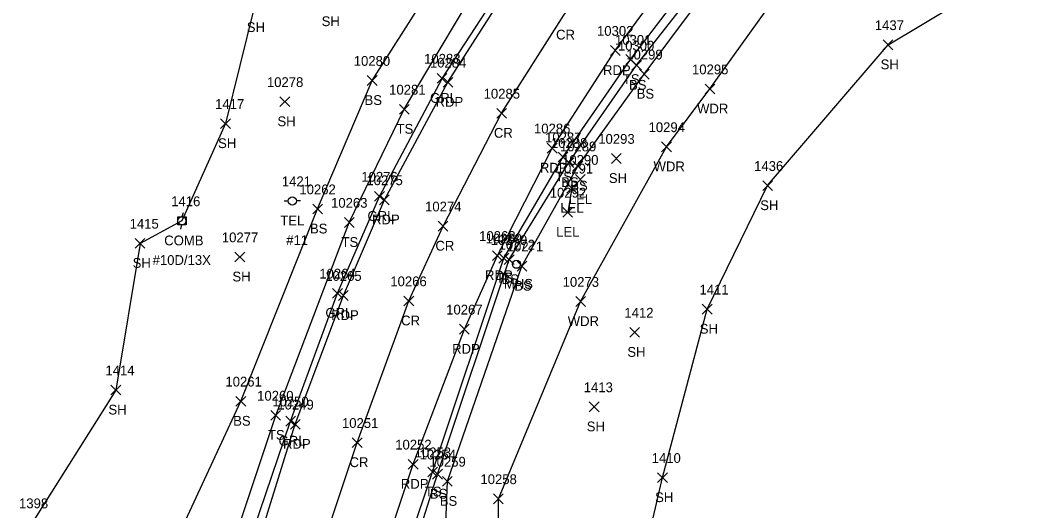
# Model space of a CAD drawing. Extents: x 1651685 to 1653558, y 889533 to 891085.
# Drawn here: x 1652735.7 to 1652940.5, y 890489.8 to 890590.1 of the extents above; entities that cross this region are included whole.
import ezdxf

# ---------------------------------------------------------------- set-up
doc = ezdxf.new("R2010")
doc.units = 0
for name, color, linetype in [('L_A', 7, 'Continuous'), ('L_I', 7, 'Continuous'), ('L_TIC', 7, 'Continuous'), ('LARO', 7, 'Continuous'), ('LAWA', 7, 'Continuous'), ('LELB', 7, 'Continuous'), ('LSOGP', 7, 'Continuous'), ('P_A', 7, 'Continuous'), ('P_I', 7, 'Continuous'), ('P_TIC', 7, 'Continuous'), ('PET', 7, 'Continuous'), ('PRC', 7, 'Continuous'), ('R_A', 7, 'Continuous'), ('R_I', 7, 'Continuous'), ('R_TIC', 7, 'Continuous'), ('RGR', 7, 'Continuous'), ('U_A', 7, 'Continuous'), ('U_C', 7, 'Continuous'), ('U_I', 7, 'Continuous'), ('UP', 7, 'Continuous'), ('USMH', 7, 'Continuous')]:
    doc.layers.add(name, color=color, linetype=linetype)

msp = doc.modelspace()

# ---------------------------------------------------------------- linework, layer by layer
at = {"layer": 'L_TIC'}
for points in [[(1652911.99, 890584.04), (1652913.99, 890586.04)], [(1652913.99, 890584.04), (1652911.99, 890586.04)], [(1652859.39, 890581.03), (1652861.39, 890583.03)], [(1652861.39, 890581.03), (1652859.39, 890583.03)], [(1652860.63, 890579.86), (1652862.63, 890581.86)], [(1652862.63, 890579.86), (1652860.63, 890581.86)], [(1652862.19, 890578.04), (1652864.19, 890580.04)], [(1652864.19, 890578.04), (1652862.19, 890580.04)], [(1652806.59, 890576.74), (1652808.59, 890578.74)], [(1652808.59, 890576.74), (1652806.59, 890578.74)], [(1652875.6, 890575.01), (1652877.6, 890577.01)], [(1652877.6, 890575.01), (1652875.6, 890577.01)], [(1652788.76, 890572.41), (1652790.76, 890574.41)], [(1652790.76, 890572.41), (1652788.76, 890574.41)], [(1652813.17, 890570.87), (1652815.17, 890572.87)], [(1652815.17, 890570.87), (1652813.17, 890572.87)], [(1652776.63, 890567.94), (1652778.63, 890569.94)], [(1652778.63, 890567.94), (1652776.63, 890569.94)], [(1652866.73, 890563.2), (1652868.73, 890565.2)], [(1652868.73, 890563.2), (1652866.73, 890565.2)], [(1652845.59, 890561.12), (1652847.59, 890563.12)], [(1652847.59, 890561.12), (1652845.59, 890563.12)], [(1652846.79, 890559.97), (1652848.79, 890561.97)], [(1652848.79, 890559.97), (1652846.79, 890561.97)], [(1652856.46, 890560.81), (1652858.46, 890562.81)], [(1652858.46, 890560.81), (1652856.46, 890562.81)], [(1652848.62, 890559.27), (1652850.62, 890561.27)], [(1652850.62, 890559.27), (1652848.62, 890561.27)], [(1652849.14, 890556.52), (1652851.14, 890558.52)], [(1652851.14, 890556.52), (1652849.14, 890558.52)], [(1652847.4, 890554.74), (1652849.4, 890556.74)], [(1652849.4, 890554.74), (1652847.4, 890556.74)], [(1652887.38, 890555.27), (1652889.38, 890557.27)], [(1652889.38, 890555.27), (1652887.38, 890557.27)], [(1652795.45, 890550.5), (1652797.45, 890552.5)], [(1652797.45, 890550.5), (1652795.45, 890552.5)], [(1652846.55, 890549.82), (1652848.55, 890551.82)], [(1652848.55, 890549.82), (1652846.55, 890551.82)], [(1652801.92, 890547.75), (1652803.92, 890549.75)], [(1652803.92, 890547.75), (1652801.92, 890549.75)], [(1652759.18, 890543.48), (1652761.18, 890545.48)], [(1652761.18, 890543.48), (1652759.18, 890545.48)], [(1652779.56, 890540.7), (1652781.56, 890542.7)], [(1652781.56, 890540.7), (1652779.56, 890542.7)], [(1652833.5, 890540.46), (1652835.5, 890542.46)], [(1652835.5, 890540.46), (1652833.5, 890542.46)], [(1652834.58, 890540.15), (1652836.58, 890542.15)], [(1652836.58, 890540.15), (1652834.58, 890542.15)], [(1652837.19, 890538.83), (1652839.19, 890540.83)], [(1652839.19, 890538.83), (1652837.19, 890540.83)], [(1652849.18, 890531.6), (1652851.18, 890533.6)], [(1652851.18, 890531.6), (1652849.18, 890533.6)], [(1652875.03, 890530.03), (1652877.03, 890532.03)], [(1652877.03, 890530.03), (1652875.03, 890532.03)], [(1652860.24, 890525.3), (1652862.24, 890527.3)], [(1652862.24, 890525.3), (1652860.24, 890527.3)], [(1652754.23, 890513.52), (1652756.23, 890515.52)], [(1652756.23, 890513.52), (1652754.23, 890515.52)], [(1652779.77, 890511.23), (1652781.77, 890513.23)], [(1652781.77, 890511.23), (1652779.77, 890513.23)], [(1652786.9, 890508.35), (1652788.9, 890510.35)], [(1652788.9, 890508.35), (1652786.9, 890510.35)], [(1652851.94, 890510.08), (1652853.94, 890512.08)], [(1652853.94, 890510.08), (1652851.94, 890512.08)], [(1652818.95, 890496.78), (1652820.95, 890498.78)], [(1652820.95, 890496.78), (1652818.95, 890498.78)], [(1652819.95, 890496.33), (1652821.95, 890498.33)], [(1652821.95, 890496.33), (1652819.95, 890498.33)], [(1652821.96, 890494.87), (1652823.96, 890496.87)], [(1652823.96, 890494.87), (1652821.96, 890496.87)], [(1652865.91, 890495.63), (1652867.91, 890497.63)], [(1652867.91, 890495.63), (1652865.91, 890497.63)], [(1652832.39, 890491.3), (1652834.39, 890493.3)], [(1652834.39, 890491.3), (1652832.39, 890493.3)]]:
    msp.add_lwpolyline(points, dxfattribs=at)
at = {"layer": 'LARO'}
msp.add_lwpolyline([(1652850.14, 890557.52), (1652848.4, 890555.74), (1652847.55, 890550.82)], dxfattribs=at)
at = {"layer": 'LAWA'}
msp.add_lwpolyline([(1652833.35, 890477.68), (1652833.39, 890492.3), (1652850.18, 890532.6), (1652867.73, 890564.2), (1652876.6, 890576.01), (1652892.95, 890598.85), (1652902.11, 890607.6), (1652908.8, 890618.44), (1652924.22, 890630.58), (1652962.12, 890654.07), (1652988.27, 890674.02), (1653019.66, 890699.72), (1653055.48, 890726.92), (1653095, 890752.3), (1653138.9, 890781.66), (1653162.63, 890798.14), (1653173.84, 890802.86)], dxfattribs=at)
at = {"layer": 'LELB'}
for points in [[(1652773.03, 890464.56), (1652787.9, 890509.35), (1652802.92, 890548.75), (1652814.17, 890571.87), (1652832.16, 890602.17), (1652848.73, 890624.66), (1652866.01, 890644.23), (1652889.12, 890668.57), (1652926.33, 890696.32), (1652964.24, 890723.35), (1652991.22, 890740.2), (1653028.13, 890766.86), (1653057.75, 890784.91), (1653079.01, 890799.53), (1653102.53, 890813.78), (1653139.28, 890840.79)], [(1652801.17, 890441.9), (1652819.95, 890497.78), (1652834.5, 890541.46), (1652846.59, 890562.12), (1652860.39, 890582.03), (1652876.07, 890602.68), (1652893.78, 890623.65), (1652912.56, 890642.08), (1652928.52, 890655.01), (1652947.04, 890668.65), (1652977.97, 890691.06), (1653009.95, 890711.96), (1653047.06, 890737.13), (1653086.67, 890762.46), (1653129.22, 890790.4), (1653161.56, 890810.77), (1653178.09, 890819.36), (1653180.64, 890814.31), (1653173.84, 890802.86)], [(1652803.19, 890441), (1652820.95, 890497.33), (1652835.58, 890541.15), (1652847.79, 890560.97), (1652861.63, 890580.86), (1652877.83, 890601.57), (1652890.21, 890617.22), (1652895.56, 890622.27), (1652897.12, 890622.95), (1652897.22, 890624.03), (1652915.57, 890639.3), (1652930.05, 890653.23), (1652948.11, 890667.03), (1652978.83, 890689.41), (1653011.67, 890709.88), (1653048.76, 890734.73), (1653087.02, 890761.14), (1653131.31, 890788.11), (1653159.98, 890805.73), (1653164.16, 890807.03), (1653164.17, 890807.66), (1653169.82, 890813.7), (1653178.09, 890819.36)], [(1652803.19, 890441), (1652822.35, 890480.19), (1652822.96, 890495.87), (1652838.19, 890539.83), (1652849.62, 890560.27), (1652863.19, 890579.04), (1652878.87, 890600.11), (1652891.82, 890615.8), (1652896.5, 890621.01), (1652897.47, 890622.7), (1652898.8, 890623.23), (1652915.57, 890639.3), (1652950.1, 890665.22), (1652980.52, 890686.66), (1653013.67, 890707.26), (1653050.87, 890733.01), (1653089.27, 890757.95), (1653133.42, 890785.98), (1653160.95, 890802.08), (1653164.63, 890804.85), (1653167.22, 890806.35), (1653170.81, 890811.17), (1653178.09, 890819.36)], [(1652740.63, 890407.57), (1652746.83, 890413.23), (1652755.32, 890445.88), (1652760.35, 890468.2), (1652780.77, 890512.23), (1652796.45, 890551.5), (1652807.59, 890577.74), (1652825.47, 890605.79), (1652840.14, 890627.46), (1652854.42, 890651.04), (1652870.71, 890668.15), (1652876.32, 890668.87), (1652880.71, 890674.05), (1652916.29, 890707.34), (1652954.78, 890736.09), (1652983.82, 890751.78), (1653022.66, 890774.83), (1653049.43, 890788.17)]]:
    msp.add_lwpolyline(points, dxfattribs=at)
at = {"layer": 'LSOGP'}
for points in [[(1653191.35, 890868.11), (1653139.25, 890847.21), (1653133.81, 890854.84), (1653132.26, 890853.62), (1653128.23, 890850.65), (1653088.88, 890824.36), (1653067.93, 890808.39), (1653036.42, 890796.38), (1653023.39, 890789.29), (1652975.72, 890758.11), (1652938.51, 890752.73), (1652900.6, 890736.09), (1652902.13, 890723.86), (1652868.79, 890705.34), (1652839.11, 890687.76), (1652822.21, 890657.08), (1652787.43, 890617.81), (1652783.5, 890592.65), (1652777.63, 890568.95), (1652768.73, 890549.07), (1652760.18, 890544.48), (1652755.23, 890514.52), (1652738.16, 890487.37)], [(1652860.84, 890470.43), (1652866.91, 890496.63), (1652876.03, 890531.03), (1652888.38, 890556.27), (1652912.99, 890585.04), (1652934.21, 890597.75), (1652965.72, 890622.73), (1652993.55, 890638.61), (1652995.94, 890655.58), (1652988.27, 890674.02), (1653019.66, 890699.72), (1653059.51, 890723.89), (1653095, 890752.3), (1653138.9, 890781.66), (1653162.63, 890798.14), (1653173.85, 890802.86), (1653182.19, 890805.28), (1653198.8, 890815.08)]]:
    msp.add_lwpolyline(points, dxfattribs=at)
at = {"layer": 'P_TIC'}
for points in [[(1652856.27, 890582.87), (1652858.27, 890584.87)], [(1652858.27, 890582.87), (1652856.27, 890584.87)], [(1652822.07, 890576.38), (1652824.07, 890578.38)], [(1652824.07, 890576.38), (1652822.07, 890578.38)], [(1652833.04, 890570.05), (1652835.04, 890572.05)], [(1652835.04, 890570.05), (1652833.04, 890572.05)], [(1652843.38, 890562.93), (1652845.38, 890564.93)], [(1652845.38, 890562.93), (1652843.38, 890564.93)], [(1652809.09, 890552.36), (1652811.09, 890554.36)], [(1652811.09, 890552.36), (1652809.09, 890554.36)], [(1652821.08, 890546.99), (1652823.08, 890548.99)], [(1652823.08, 890546.99), (1652821.08, 890548.99)], [(1652832.17, 890540.97), (1652834.17, 890542.97)], [(1652834.17, 890540.97), (1652832.17, 890542.97)], [(1652800.72, 890532.82), (1652802.72, 890534.82)], [(1652802.72, 890532.82), (1652800.72, 890534.82)], [(1652814.08, 890531.72), (1652816.08, 890533.72)], [(1652816.08, 890531.72), (1652814.08, 890533.72)], [(1652825.44, 890525.94), (1652827.44, 890527.94)], [(1652827.44, 890525.94), (1652825.44, 890527.94)], [(1652790.9, 890506.53), (1652792.9, 890508.53)], [(1652792.9, 890506.53), (1652790.9, 890508.53)], [(1652803.54, 890502.78), (1652805.54, 890504.78)], [(1652805.54, 890502.78), (1652803.54, 890504.78)], [(1652814.98, 890498.36), (1652816.98, 890500.36)], [(1652816.98, 890498.36), (1652814.98, 890500.36)]]:
    msp.add_lwpolyline(points, dxfattribs=at)
at = {"layer": 'PET'}
for points in [[(1652776.68, 890458.63), (1652791.9, 890507.53), (1652801.72, 890533.82), (1652810.09, 890553.36), (1652823.07, 890577.38), (1652836.65, 890598.71), (1652853.5, 890620.62), (1652874.5, 890644.55), (1652894.69, 890663.43), (1652909.83, 890677.02), (1652929.28, 890691.96), (1652967.44, 890717.98), (1652993.7, 890736.14), (1653032.31, 890761.89), (1653070.4, 890786.93), (1653112.15, 890813.99), (1653148.48, 890837.47), (1653192.87, 890865.71), (1653235.94, 890893.09), (1653280.18, 890921.16), (1653320.29, 890946.68)], [(1652797.7, 890444.76), (1652815.98, 890499.36), (1652826.44, 890526.94), (1652833.17, 890541.97), (1652844.38, 890563.93), (1652857.27, 890583.87), (1652872.84, 890604.95), (1652891.59, 890626.08), (1652910.84, 890643.86), (1652926.01, 890657.3), (1652944.49, 890672.05), (1652975.79, 890694.46), (1653007.52, 890715.91), (1653044.82, 890740.95), (1653083.79, 890766.34), (1653126.92, 890794.39), (1653162.42, 890817.19), (1653177.23, 890826.53), (1653212.82, 890849.27), (1653251.6, 890873.99), (1653294.22, 890900.69), (1653334.65, 890925.85)]]:
    msp.add_lwpolyline(points, dxfattribs=at)
at = {"layer": 'PRC'}
msp.add_lwpolyline([(1652786.21, 890448.94), (1652804.54, 890503.78), (1652815.08, 890532.72), (1652822.08, 890547.99), (1652834.04, 890571.05), (1652846.73, 890591.11), (1652862.72, 890612.73), (1652882.99, 890635.62), (1652902.76, 890654.37), (1652917.73, 890667.19), (1652936.47, 890681.71), (1652967.99, 890703.84), (1653000.43, 890726.04), (1653038.85, 890751.54), (1653077.14, 890776.73), (1653119.4, 890804.03), (1653156.21, 890827.39), (1653198.86, 890855.33), (1653243.54, 890883.44), (1653287.35, 890911.24), (1653327.74, 890936.2)], dxfattribs=at)
at = {"layer": 'R_TIC'}
for points in [[(1652820.88, 890577.18), (1652822.88, 890579.18)], [(1652822.88, 890577.18), (1652820.88, 890579.18)], [(1652808.1, 890553.07), (1652810.1, 890555.07)], [(1652810.1, 890553.07), (1652808.1, 890555.07)], [(1652799.51, 890533.29), (1652801.51, 890535.29)], [(1652801.51, 890533.29), (1652799.51, 890535.29)], [(1652789.93, 890507.17), (1652791.93, 890509.17)], [(1652791.93, 890507.17), (1652789.93, 890509.17)]]:
    msp.add_lwpolyline(points, dxfattribs=at)
at = {"layer": 'RGR'}
msp.add_lwpolyline([(1652753.62, 890407.5), (1652763.75, 890431.04), (1652774.48, 890459.79), (1652790.93, 890508.17), (1652800.51, 890534.29), (1652809.1, 890554.07), (1652821.88, 890578.18), (1652835.53, 890599.08), (1652852.44, 890621.25), (1652873.86, 890645.38), (1652894.3, 890664.88), (1652909.53, 890677.55), (1652928.71, 890692.69), (1652967.13, 890720.62), (1652991.99, 890738.03), (1653030.5, 890764.27), (1653069.01, 890789.08), (1653110.73, 890816.31), (1653147.12, 890839.54), (1653191.34, 890868.1), (1653234.07, 890895.44), (1653279.07, 890923.79), (1653318.83, 890948.74)], dxfattribs=at)
at = {"layer": 'UP'}
for p, q in [((1652789.62, 890553.14), (1652790.44, 890553.14)), ((1652791.28, 890553.14), (1652791.28, 890553.14)), ((1652792.94, 890553.14), (1652792.11, 890553.14)), ((1652792.11, 890553.14), (1652792.11, 890553.14)), ((1652792.94, 890553.14), (1652792.94, 890553.14)), ((1652767.9, 890548.24), (1652767.9, 890549.91)), ((1652767.9, 890549.91), (1652769.57, 890549.91)), ((1652768.98, 890550.74), (1652768.73, 890549.91)), ((1652769.57, 890549.91), (1652769.57, 890548.24)), ((1652769.57, 890548.24), (1652767.9, 890548.24)), ((1652768.48, 890547.41), (1652768.73, 890548.24)), ((1652768.73, 890549.07), (1652768.73, 890549.07))]:
    msp.add_line(p, q, dxfattribs=at)
for centre in [(1652791.28, 890553.14), (1652768.73, 890549.07)]:
    msp.add_circle(centre, 0.833, dxfattribs=at)
at = {"layer": 'USMH'}
for p, q in [((1652837.09, 890540.21), (1652837.09, 890540.21)), ((1652837.92, 890540.21), (1652837.92, 890540.21))]:
    msp.add_line(p, q, dxfattribs=at)
msp.add_circle((1652837.09, 890540.21), 0.833, dxfattribs=at)

# ---------------------------------------------------------------- texts
at = {"layer": 'L_A'}
for s, p in [('SH', (1652797.28, 890588.85)), ('SH', (1652781.99, 890587.64)), ('SH', (1652911.47, 890580.04)), ('TS', (1652858.8, 890577.03)), ('BS', (1652860.07, 890575.86)), ('BS', (1652861.63, 890574.04)), ('BS', (1652806.04, 890572.74)), ('WDR', (1652873.97, 890571.01)), ('SH', (1652788.25, 890568.41)), ('TS', (1652812.58, 890566.87)), ('SH', (1652776.12, 890563.94)), ('WDR', (1652865.09, 890559.2)), ('TS', (1652845, 890557.12)), ('BS', (1652846.23, 890555.97)), ('SH', (1652855.95, 890556.81)), ('BS', (1652848.07, 890555.27)), ('LEL', (1652847.78, 890552.52)), ('SH', (1652886.87, 890551.27)), ('LEL', (1652846.04, 890550.74)), ('BS', (1652794.89, 890546.5)), ('LEL', (1652845.19, 890545.82)), ('TS', (1652801.33, 890543.75)), ('SH', (1652758.67, 890539.48)), ('SH', (1652779.05, 890536.7)), ('TS', (1652832.91, 890536.46)), ('BS', (1652834.02, 890536.15)), ('BS', (1652836.63, 890534.83)), ('WDR', (1652847.55, 890527.6)), ('SH', (1652874.52, 890526.03)), ('SH', (1652859.73, 890521.3)), ('SH', (1652753.72, 890509.52)), ('BS', (1652779.21, 890507.23)), ('TS', (1652786.31, 890504.35)), ('SH', (1652851.43, 890506.08)), ('TS', (1652818.36, 890492.78)), ('BS', (1652819.39, 890492.33)), ('BS', (1652821.41, 890490.87)), ('SH', (1652865.4, 890491.63))]:
    msp.add_text(s, height=2, dxfattribs=at).set_placement(p)
at = {"layer": 'L_I'}
for s, p in [('1437', (1652910.29, 890588.04)), ('10301', (1652857.21, 890585.03)), ('10300', (1652857.8, 890583.86)), ('10299', (1652859.51, 890582.04)), ('10280', (1652803.84, 890580.74)), ('10295', (1652872.94, 890579.01)), ('10278', (1652786.1, 890576.41)), ('10281', (1652811.07, 890574.87)), ('1417', (1652775.51, 890571.94)), ('10294', (1652864.06, 890567.2)), ('10287', (1652842.92, 890565.12)), ('10288', (1652844.12, 890563.97)), ('10293', (1652853.79, 890564.81)), ('10289', (1652845.95, 890563.27)), ('10290', (1652846.39, 890560.52)), ('10291', (1652845.3, 890558.74)), ('1436', (1652885.63, 890559.27)), ('10262', (1652792.73, 890554.5)), ('10292', (1652843.88, 890553.82)), ('10263', (1652799.2, 890551.75)), ('1415', (1652758.05, 890547.48)), ('10277', (1652776.89, 890544.7)), ('10269', (1652830.77, 890544.46)), ('10270', (1652831.82, 890544.15)), ('10271', (1652835.09, 890542.83)), ('10273', (1652846.51, 890535.6)), ('1411', (1652874.47, 890534.03)), ('1412', (1652859.12, 890529.3)), ('1414', (1652753.11, 890517.52)), ('10261', (1652777.62, 890515.23)), ('10260', (1652784.1, 890512.35)), ('1413', (1652850.82, 890514.08)), ('10253', (1652816.28, 890500.78)), ('10254', (1652817.28, 890500.33)), ('10259', (1652819.29, 890498.87)), ('1410', (1652864.7, 890499.63)), ('10258', (1652829.72, 890495.3)), ('1398', (1652735.46, 890490.37))]:
    msp.add_text(s, height=2, dxfattribs=at).set_placement(p)
at = {"layer": 'P_A'}
for s, p in [('CR', (1652845.17, 890586.11)), ('RDP', (1652854.76, 890578.87)), ('RDP', (1652820.56, 890572.38)), ('CR', (1652832.47, 890566.05)), ('RDP', (1652841.87, 890558.93)), ('RDP', (1652807.58, 890548.36)), ('CR', (1652820.52, 890542.99)), ('RDP', (1652830.66, 890536.97)), ('RDP', (1652799.21, 890528.82)), ('CR', (1652813.52, 890527.72)), ('RDP', (1652823.93, 890521.94)), ('RDP', (1652789.39, 890502.53)), ('CR', (1652802.97, 890498.78)), ('RDP', (1652813.46, 890494.36))]:
    msp.add_text(s, height=2, dxfattribs=at).set_placement(p)
at = {"layer": 'P_I'}
for s, p in [('10302', (1652853.53, 890586.87)), ('10284', (1652819.4, 890580.38)), ('10285', (1652830.37, 890574.05)), ('10286', (1652840.66, 890566.93)), ('10275', (1652806.42, 890556.36)), ('10274', (1652818.41, 890550.99)), ('10268', (1652829.45, 890544.97)), ('10265', (1652798.01, 890536.82)), ('10266', (1652811.31, 890535.72)), ('10267', (1652822.72, 890529.94)), ('10249', (1652788.23, 890510.53)), ('10251', (1652801.43, 890506.78)), ('10252', (1652812.31, 890502.36))]:
    msp.add_text(s, height=2, dxfattribs=at).set_placement(p)
at = {"layer": 'R_A'}
for p in [(1652819.43, 890573.18), (1652806.64, 890549.07), (1652798.05, 890529.29), (1652788.48, 890503.17)]:
    msp.add_text('GRL', height=2, dxfattribs=at).set_placement(p)
at = {"layer": 'R_I'}
for s, p in [('10283', (1652818.21, 890581.18)), ('10276', (1652805.38, 890557.07)), ('10264', (1652796.79, 890537.29)), ('10250', (1652787.18, 890511.17))]:
    msp.add_text(s, height=2, dxfattribs=at).set_placement(p)
at = {"layer": 'U_A'}
for s, p in [('TEL', (1652788.83, 890548.14)), ('COMB', (1652765.12, 890544.07)), ('MHS', (1652834.51, 890535.21))]:
    msp.add_text(s, height=2, dxfattribs=at).set_placement(p)
at = {"layer": 'U_C'}
for s, p in [('#11', (1652790.05, 890544.14)), ('#10D/13X', (1652762.75, 890540.07))]:
    msp.add_text(s, height=2, dxfattribs=at).set_placement(p)
at = {"layer": 'U_I'}
for s, p in [('1421', (1652789.15, 890556.14)), ('1416', (1652766.55, 890552.07)), ('10272', (1652833.42, 890543.21))]:
    msp.add_text(s, height=2, dxfattribs=at).set_placement(p)

doc.saveas('drawing.dxf')
